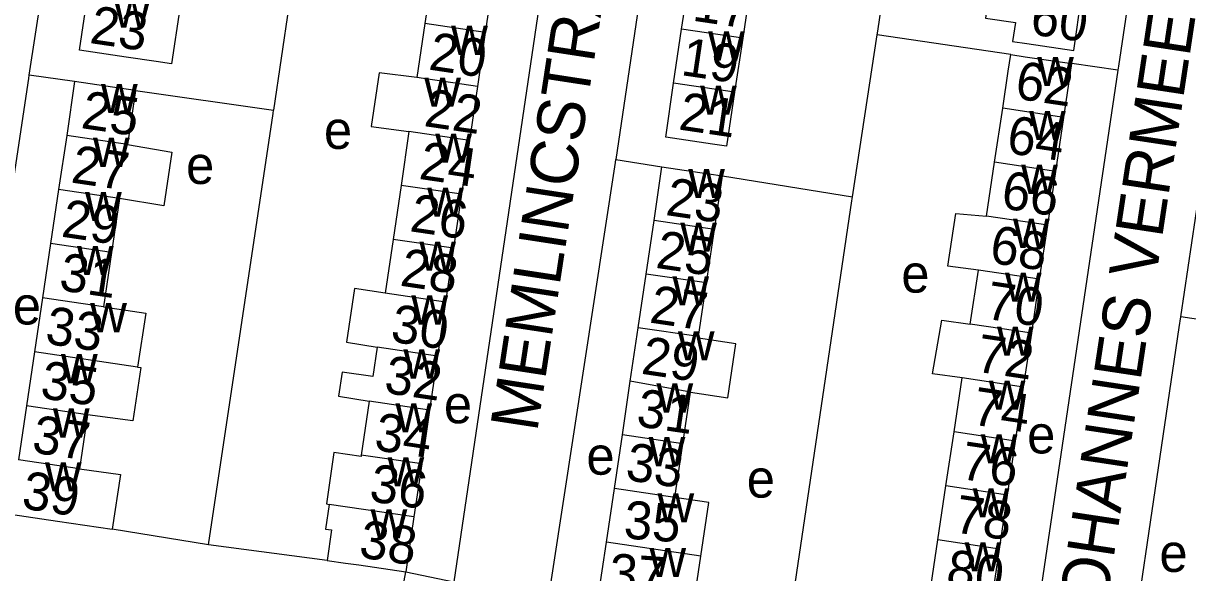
# Model space of a CAD drawing. Extents: x 163012 to 165277, y 382513 to 383987.
# Drawn here: x 163733.4 to 163856.2, y 383005.9 to 383063.8 of the extents above; entities that cross this region are included whole.
import ezdxf

# ---------------------------------------------------------------- set-up
doc = ezdxf.new("R2010")
doc.units = 0
for name, color, linetype in [('BLT_Basislijn', 7, 'Continuous'), ('BLT_Bebouwing', 7, 'Continuous'), ('BLT_Centroide', 7, 'Continuous'), ('BLT_Huisnummer', 7, 'Continuous'), ('BLT_Huisnummer_ tussenligend', 7, 'Continuous'), ('BLT_Onderverdeling_panden', 7, 'Continuous'), ('BLT_Straatnaam', 7, 'Continuous')]:
    doc.layers.add(name, color=color, linetype=linetype)

msp = doc.modelspace()

# ---------------------------------------------------------------- linework, layer by layer
at = {"layer": 'BLT_Basislijn'}
for p, q in [((163734.06, 383058.34), (163744.11, 383124.46)), ((163805.66, 383115.2), (163795.92, 383049.43)), ((163855.5, 383032.85), (163866.08, 383104.4)), ((163820.88, 383045.5), (163823.49, 383062.58)), ((163837.56, 383060.5), (163823.49, 383062.58)), ((163848.86, 383058.88), (163843.99, 383059.57)), ((163738.84, 383057.68), (163734.06, 383058.34)), ((163745.26, 383056.73), (163759.81, 383054.63)), ((163795.92, 383049.43), (163800.78, 383048.67)), ((163807.15, 383047.73), (163820.88, 383045.5)), ((163860.31, 383032.12), (163855.5, 383032.85)), ((163752.94, 383008.8), (163742.81, 383010.46)), ((163765.47, 383007.15), (163752.94, 383008.8)), ((163769.45, 382982.9), (163773.76, 383005.95)), ((163773.76, 383005.95), (163778.82, 383004.9))]:
    msp.add_line(p, q, dxfattribs=at)
for points in [[(163823.49, 383062.58), (163823.55, 383062.97), (163830.4, 383109.71)], [(163855.87, 383106.07), (163848.92, 383059.29), (163848.86, 383058.88)], [(163762.3, 383071.48), (163762.25, 383071.12), (163759.81, 383054.63)], [(163788.12, 383067.75), (163788.07, 383067.4), (163778.82, 383004.9)], [(163848.86, 383058.88), (163837.81, 382984.44)], [(163727.17, 383012.54), (163734.01, 383057.97), (163734.06, 383058.34)], [(163752.94, 383008.8), (163759.76, 383054.28), (163759.81, 383054.63)], [(163787.87, 382991.74), (163787.1, 382991.85), (163795.88, 383049.14), (163795.92, 383049.43)], [(163812.36, 382988.05), (163820.82, 383045.09), (163820.88, 383045.5)], [(163848.1, 382982.79), (163855.33, 383031.73), (163855.5, 383032.85)]]:
    msp.add_lwpolyline(points, dxfattribs=at)
at = {"layer": 'BLT_Bebouwing'}
for p, q in [((163776.62, 383069.46), (163775.78, 383063.77)), ((163802.85, 383063.19), (163803.7, 383068.9)), ((163782.99, 383068.52), (163782.15, 383062.83)), ((163810.13, 383067.94), (163809.29, 383062.24)), ((163775.78, 383063.77), (163774.94, 383058.09)), ((163782.15, 383062.83), (163781.31, 383057.15)), ((163802.01, 383057.49), (163802.85, 383063.19)), ((163809.29, 383062.24), (163808.44, 383056.54)), ((163738.84, 383057.68), (163738, 383051.98)), ((163745.26, 383056.73), (163744.41, 383051.03)), ((163781.31, 383057.15), (163780.47, 383051.46)), ((163835.86, 383049.15), (163836.71, 383054.84)), ((163842.3, 383048.19), (163843.15, 383053.88)), ((163738, 383051.98), (163737.15, 383046.27)), ((163774.1, 383052.4), (163773.26, 383046.71)), ((163780.47, 383051.46), (163779.63, 383045.77)), ((163835, 383043.46), (163835.86, 383049.15)), ((163799.95, 383043.02), (163800.78, 383048.67)), ((163841.46, 383042.5), (163842.3, 383048.19)), ((163773.26, 383046.71), (163772.42, 383041.02)), ((163806.32, 383042.07), (163807.15, 383047.73)), ((163737.15, 383046.27), (163736.31, 383040.57)), ((163743.57, 383045.32), (163742.72, 383039.62)), ((163779.63, 383045.77), (163778.79, 383040.08)), ((163799.11, 383037.36), (163799.95, 383043.02)), ((163805.48, 383036.42), (163806.32, 383042.07)), ((163840.61, 383036.81), (163841.46, 383042.5)), ((163736.31, 383040.57), (163735.46, 383034.86)), ((163772.42, 383041.02), (163771.58, 383035.33)), ((163742.72, 383039.62), (163741.88, 383033.91)), ((163778.79, 383040.08), (163777.95, 383034.39)), ((163798.27, 383031.7), (163799.11, 383037.36)), ((163833.29, 383032.08), (163834.15, 383037.77)), ((163839.77, 383031.12), (163840.61, 383036.81)), ((163804.64, 383030.76), (163805.48, 383036.42)), ((163735.46, 383034.86), (163734.62, 383029.16)), ((163777.95, 383034.39), (163777.12, 383028.71)), ((163797.43, 383026.05), (163798.27, 383031.7)), ((163838.92, 383025.43), (163839.77, 383031.12)), ((163734.62, 383029.16), (163733.77, 383023.46)), ((163777.12, 383028.71), (163776.28, 383023.02)), ((163796.6, 383020.39), (163797.43, 383026.05)), ((163831.58, 383020.71), (163832.44, 383026.4)), ((163802.97, 383019.45), (163803.78, 383024.91)), ((163838.08, 383019.74), (163838.92, 383025.43)), ((163733.77, 383023.46), (163732.93, 383017.75)), ((163769.9, 383023.96), (163769.07, 383018.27)), ((163740.19, 383022.51), (163739.34, 383016.8)), ((163776.28, 383023.02), (163775.44, 383017.33)), ((163795.76, 383014.73), (163796.6, 383020.39)), ((163830.73, 383015.02), (163831.58, 383020.71)), ((163837.23, 383014.05), (163838.08, 383019.74)), ((163802.13, 383013.79), (163802.97, 383019.45)), ((163775.44, 383017.33), (163774.62, 383011.76)), ((163794.92, 383009.08), (163795.76, 383014.73)), ((163829.87, 383009.33), (163830.73, 383015.02)), ((163836.38, 383008.36), (163837.23, 383014.05)), ((163774.62, 383011.76), (163773.76, 383005.95)), ((163829.02, 383003.65), (163829.87, 383009.33)), ((163835.54, 383002.68), (163836.38, 383008.36))]:
    msp.add_line(p, q, dxfattribs=at)
for points in [[(163835.48, 383068.21), (163834.91, 383064.34), (163838.05, 383063.88), (163837.76, 383061.88), (163839.25, 383061.66), (163844.2, 383060.94), (163845.03, 383066.67)], [(163746.61, 383065.84), (163749.93, 383065.35), (163749.07, 383059.52), (163747.44, 383059.76), (163744.29, 383060.22), (163739.34, 383060.96), (163740.18, 383066.67)], [(163836.71, 383054.84), (163837.3, 383058.77), (163837.56, 383060.5)], [(163837.56, 383060.5), (163839.08, 383060.28), (163843.99, 383059.57)], [(163843.15, 383053.88), (163843.68, 383057.42), (163843.99, 383059.57)], [(163745.26, 383056.73), (163743.79, 383056.94), (163738.84, 383057.68)], [(163774.94, 383058.09), (163770.94, 383058.57), (163770.11, 383052.91), (163774.1, 383052.4)], [(163808.44, 383056.54), (163807.6, 383050.83), (163806.11, 383051.05), (163801.17, 383051.78), (163802.01, 383057.49)], [(163744.41, 383051.03), (163749.09, 383050.22), (163748.25, 383044.55), (163743.57, 383045.32)], [(163800.78, 383048.67), (163805.73, 383047.94), (163807.15, 383047.73)], [(163834.15, 383037.77), (163830.93, 383038.18), (163831.76, 383043.75), (163835, 383043.46)], [(163771.58, 383035.33), (163768.34, 383035.82), (163767.51, 383030.16), (163770.74, 383029.64)], [(163741.88, 383033.91), (163746.33, 383033.25), (163745.48, 383027.55)], [(163832.44, 383026.4), (163829.32, 383026.85), (163830.28, 383032.49), (163833.29, 383032.08)], [(163803.78, 383024.91), (163807.73, 383024.32), (163808.57, 383029.99), (163804.62, 383030.58), (163804.64, 383030.76)], [(163770.74, 383029.64), (163770.29, 383026.54), (163767.04, 383027.01), (163766.68, 383024.49), (163769.9, 383023.96)], [(163745.48, 383027.55), (163745.81, 383027.5), (163744.98, 383021.88), (163740.19, 383022.51)], [(163769.07, 383018.27), (163769.04, 383018.11), (163766.19, 383018.54), (163765.39, 383013.12), (163765.67, 383013.07)], [(163739.34, 383016.8), (163743.66, 383016.22), (163742.81, 383010.46)], [(163804.87, 383007.6), (163805.71, 383013.28), (163802.13, 383013.79)], [(163765.67, 383013.07), (163765.29, 383010.47), (163765.94, 383010.37), (163765.47, 383007.15)], [(163732.08, 383012.05), (163737.03, 383011.31), (163742.81, 383010.46)], [(163795.06, 383002.87), (163794.71, 383002.92), (163794.03, 383003.02), (163794.92, 383009.08)], [(163802.89, 383001.71), (163802.95, 383002.11), (163804.03, 383001.95), (163804.87, 383007.6)], [(163765.47, 383007.15), (163767.39, 383006.88)], [(163767.39, 383006.88), (163768.81, 383006.68), (163773.76, 383005.95)]]:
    msp.add_lwpolyline(points, dxfattribs=at)
at = {"layer": 'BLT_Onderverdeling_panden'}
for p, q in [((163782.15, 383062.83), (163775.78, 383063.77)), ((163809.29, 383062.24), (163802.85, 383063.19)), ((163781.31, 383057.15), (163774.94, 383058.09)), ((163808.44, 383056.54), (163802.01, 383057.49)), ((163843.15, 383053.88), (163836.71, 383054.84)), ((163744.41, 383051.03), (163738, 383051.98)), ((163780.47, 383051.46), (163774.1, 383052.4)), ((163842.3, 383048.19), (163835.86, 383049.15)), ((163779.63, 383045.77), (163773.26, 383046.71)), ((163743.57, 383045.32), (163737.15, 383046.27)), ((163806.32, 383042.07), (163799.95, 383043.02)), ((163841.46, 383042.5), (163835, 383043.46)), ((163742.72, 383039.62), (163736.31, 383040.57)), ((163778.79, 383040.08), (163772.42, 383041.02)), ((163805.48, 383036.42), (163799.11, 383037.36)), ((163840.61, 383036.81), (163834.15, 383037.77)), ((163741.88, 383033.91), (163735.46, 383034.86)), ((163777.95, 383034.39), (163771.58, 383035.33)), ((163839.77, 383031.12), (163833.29, 383032.08)), ((163804.64, 383030.76), (163798.27, 383031.7)), ((163777.12, 383028.71), (163770.74, 383029.64)), ((163745.48, 383027.55), (163734.62, 383029.16)), ((163803.78, 383024.91), (163797.43, 383026.05)), ((163838.92, 383025.43), (163832.44, 383026.4)), ((163740.19, 383022.51), (163733.77, 383023.46)), ((163776.28, 383023.02), (163769.9, 383023.96)), ((163802.97, 383019.45), (163796.6, 383020.39)), ((163838.08, 383019.74), (163831.58, 383020.71)), ((163775.44, 383017.33), (163769.07, 383018.27)), ((163739.34, 383016.8), (163732.93, 383017.75)), ((163802.13, 383013.79), (163795.76, 383014.73)), ((163837.23, 383014.05), (163830.73, 383015.02)), ((163774.62, 383011.76), (163765.67, 383013.07)), ((163804.87, 383007.6), (163794.92, 383009.08)), ((163836.38, 383008.36), (163829.87, 383009.33))]:
    msp.add_line(p, q, dxfattribs=at)

# ---------------------------------------------------------------- texts
at = {"layer": 'BLT_Centroide'}
for s, p in [('w', (163742.96, 383063.34)), ('w', (163778.55, 383060.47)), ('w', (163805.65, 383059.88)), ('w', (163840.35, 383057.19)), ('w', (163775.71, 383055)), ('w', (163741.62, 383054.34)), ('w', (163804.8, 383054.16)), ('w', (163839.5, 383051.5)), ('e', (163765.13, 383050.56)), ('w', (163740.78, 383048.66)), ('w', (163776.87, 383049.09)), ('e', (163750.59, 383046.86)), ('w', (163803.55, 383045.38)), ('w', (163838.66, 383045.81)), ('w', (163739.94, 383042.94)), ('w', (163776.02, 383043.41)), ('w', (163837.8, 383040.12)), ('w', (163802.71, 383039.72)), ('w', (163775.19, 383037.72)), ('w', (163739.09, 383037.25)), ('e', (163826.02, 383035.4)), ('w', (163801.88, 383034.06)), ('w', (163836.95, 383034.44)), ('e', (163732.32, 383032.04)), ('w', (163740.48, 383031.22)), ('w', (163774.35, 383032.03)), ('w', (163836.11, 383028.75)), ('w', (163802.46, 383028.25)), ('w', (163773.51, 383026.34)), ('w', (163737.4, 383025.84)), ('w', (163800.2, 383022.75)), ('w', (163835.25, 383023.06)), ('e', (163777.78, 383021.62)), ('w', (163736.55, 383020.12)), ('w', (163772.67, 383020.66)), ('e', (163839.29, 383018.44)), ('w', (163799.37, 383017.09)), ('w', (163834.4, 383017.38)), ('e', (163792.81, 383016.2)), ('w', (163735.71, 383014.44)), ('w', (163771.84, 383014.97)), ('e', (163809.72, 383013.78)), ('w', (163833.55, 383011.69)), ('w', (163800.31, 383011.16)), ('w', (163770.05, 383009.47)), ('w', (163799.46, 383005.41)), ('w', (163832.7, 383006)), ('e', (163853.24, 383005.95))]:
    msp.add_text(s, height=4, dxfattribs=at).set_placement(p)
at = {"layer": 'BLT_Huisnummer'}
for s, rotation, p in [('17', 351.5834, (163803.89, 383064.1)), ('60', 351.7041, (163839.49, 383062.67)), ('23', 351.5718, (163740.32, 383061.74)), ('62', 351.5414, (163837.9, 383055.89)), ('25', 351.575, (163739.41, 383052.77)), ('22', 351.6082, (163775.58, 383052.98)), ('21', 351.5834, (163802.43, 383052.62)), ('66', 351.546, (163836.43, 383044.32)), ('23', 351.5818, (163801.06, 383043.6)), ('26', 351.6082, (163774.08, 383041.89)), ('29', 351.5737, (163737.33, 383041.32)), ('27', 351.5818, (163799.36, 383032.26)), ('70', 351.5432, (163834.8, 383032.66)), ('33', 351.5737, (163735.62, 383030.04)), ('30', 351.617, (163772.05, 383030.25)), ('31', 351.5906, (163797.96, 383021.34)), ('74', 351.5478, (163833.37, 383021.51)), ('34', 351.6069, (163770.32, 383018.82)), ('39', 351.5718, (163733.14, 383012.66)), ('35', 355.8066, (163796.67, 383009.49)), ('78', 351.5421, (163831.49, 383010.14)), ('38', 351.6041, (163768.71, 383007.5))]:
    msp.add_text(s, height=4, rotation=rotation, dxfattribs=at).set_placement(p)
at = {"layer": 'BLT_Huisnummer_ tussenligend'}
for s, rotation, p in [('20', 351.6154, (163776.07, 383058.94)), ('19', 351.5834, (163802.68, 383058.36)), ('64', 351.5414, (163837.01, 383050.15)), ('27', 351.575, (163738.35, 383047.03)), ('24', 351.6082, (163775.05, 383047.41)), ('25', 351.5818, (163800.02, 383038.03)), ('68', 351.546, (163835.22, 383038.57)), ('31', 351.5737, (163737.09, 383035.68)), ('28', 351.6082, (163773.05, 383036.15)), ('29', 351.5818, (163798.49, 383026.86)), ('72', 351.5432, (163833.77, 383027.09)), ('35', 351.5737, (163735.1, 383024.3)), ('32', 351.617, (163771.37, 383024.85)), ('37', 351.5737, (163734.22, 383018.56)), ('33', 351.5906, (163796.82, 383015.66)), ('76', 351.5478, (163832.15, 383015.77)), ('36', 351.6069, (163769.8, 383013.42)), ('37', 355.8066, (163795.09, 383003.93)), ('80', 351.5421, (163830.61, 383004.4))]:
    msp.add_text(s, height=4, rotation=rotation, dxfattribs=at).set_placement(p)
at = {"layer": 'BLT_Straatnaam'}
for s, rotation, p in [('ROGIER VAN DER WEYDENSTRAAT', 81.5474, (163724.32, 383017.21)), ('JOHANNES VERMEERSTRAAT', 81.3957, (163847.12, 382998.83)), ('MEMLINCSTRAAT', 81.2951, (163787.61, 383020.62))]:
    msp.add_text(s, height=5, rotation=rotation, dxfattribs=at).set_placement(p)

doc.saveas('drawing.dxf')
